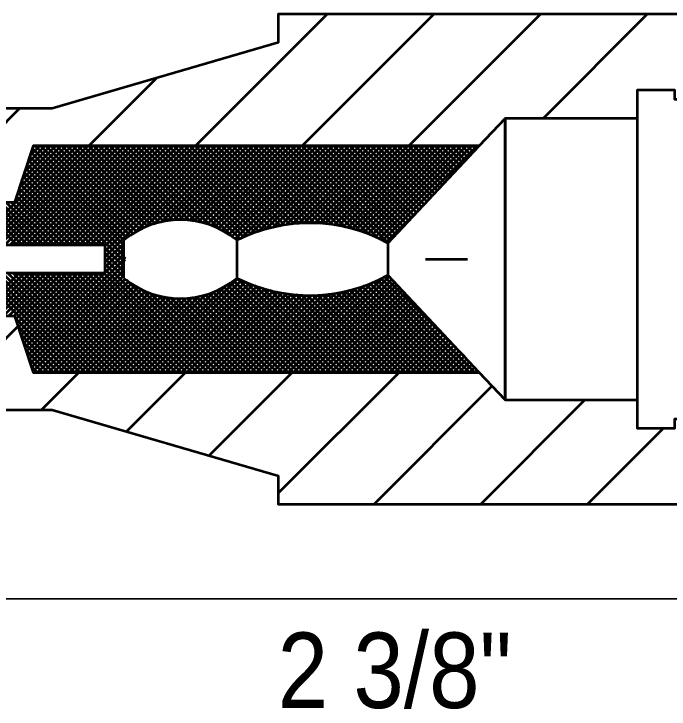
# Model space of a CAD drawing. Extents: x -1 to 679, y 0 to 440.
# Drawn here: x 477.92 to 495.29, y 208.75 to 227.17 of the extents above; entities that cross this region are included whole.
import ezdxf

# ---------------------------------------------------------------- set-up
doc = ezdxf.new("R2010")
doc.units = 0
doc.header["$LTSCALE"] = 0.8
doc.layers.add('1', color=7, linetype='Continuous', lineweight=53)

msp = doc.modelspace()

# ---------------------------------------------------------------- linework, layer by layer
at = {"layer": '1'}
for p, q in [((482.7369, 223.6716), (486.2369, 227.1716)), ((485.5653, 223.6716), (489.0653, 227.1716)), ((488.3938, 223.6716), (491.8938, 227.1716)), ((491.9503, 224.3997), (494.7222, 227.1716)), ((479.9085, 223.6716), (481.7207, 225.4837)), ((475.5801, 222.1716), (478.0801, 224.6716)), ((490.9453, 224.3997), (490.2599, 223.6716)), ((494.4453, 224.3997), (494.4453, 216.9434)), ((476.8324, 221.0466), (479.4574, 223.6716)), ((476.9738, 221.0466), (479.5988, 223.6716)), ((477.1153, 221.0466), (479.7403, 223.6716)), ((477.2567, 221.0466), (479.8817, 223.6716)), ((477.3981, 221.0466), (480.0231, 223.6716)), ((477.5396, 221.0466), (480.1646, 223.6716)), ((477.681, 221.0466), (480.306, 223.6716)), ((477.8224, 221.0466), (480.4474, 223.6716)), ((477.9638, 221.0466), (480.5888, 223.6716)), ((477.996, 222.3516), (479.316, 223.6716)), ((478.0667, 222.5637), (479.1746, 223.6716)), ((478.1053, 221.0466), (480.7303, 223.6716)), ((478.1374, 222.7758), (479.0332, 223.6716)), ((478.2081, 222.9879), (478.8918, 223.6716)), ((478.2467, 221.0466), (480.8717, 223.6716)), ((478.2788, 223.2001), (478.7503, 223.6716)), ((478.3496, 223.4123), (478.6089, 223.6716)), ((478.3881, 221.0466), (481.0131, 223.6716)), ((480.8408, 221.1752), (478.4131, 223.6029)), ((478.4203, 223.6243), (478.4675, 223.6716)), ((480.9218, 221.2357), (478.4859, 223.6716)), ((478.5295, 221.0466), (481.1545, 223.6716)), ((481.0028, 221.2961), (478.6273, 223.6716)), ((478.6709, 221.0466), (481.2959, 223.6716)), ((481.0887, 221.3517), (478.7688, 223.6716)), ((478.8123, 221.0466), (481.4373, 223.6716)), ((481.1773, 221.4044), (478.9102, 223.6716)), ((478.9537, 221.0466), (481.5787, 223.6716)), ((481.2681, 221.4551), (479.0516, 223.6716)), ((479.0952, 221.0466), (481.7202, 223.6716)), ((481.3648, 221.4997), (479.193, 223.6716)), ((479.2366, 221.0466), (481.8616, 223.6716)), ((481.4617, 221.5443), (479.3344, 223.6716)), ((479.378, 221.0466), (482.003, 223.6716)), ((481.5668, 221.5806), (479.4758, 223.6716)), ((479.5194, 221.0466), (482.1444, 223.6716)), ((481.6724, 221.6164), (479.6172, 223.6716)), ((479.6608, 221.0466), (482.2858, 223.6716)), ((481.7852, 221.645), (479.7587, 223.6716)), ((479.8022, 221.0466), (482.4272, 223.6716)), ((481.9006, 221.6711), (479.9001, 223.6716)), ((479.9437, 221.0466), (482.5687, 223.6716)), ((482.0233, 221.6898), (480.0415, 223.6716)), ((480.0852, 221.0466), (482.7102, 223.6716)), ((482.1498, 221.7047), (480.1829, 223.6716)), ((480.2266, 221.0466), (482.8516, 223.6716)), ((482.286, 221.7099), (480.3243, 223.6716)), ((480.336, 221.0146), (482.993, 223.6716)), ((480.336, 220.8732), (483.1344, 223.6716)), ((480.336, 220.7318), (483.2758, 223.6716)), ((482.4257, 221.7117), (480.4657, 223.6716)), ((482.5811, 221.6977), (480.6072, 223.6716)), ((482.7453, 221.6748), (480.7486, 223.6716)), ((482.9232, 221.6384), (480.89, 223.6716)), ((483.1284, 221.5747), (481.0315, 223.6716)), ((481.11, 221.3643), (483.4172, 223.6716)), ((483.3722, 221.4723), (481.1729, 223.6716)), ((483.7456, 221.2403), (481.3143, 223.6716)), ((481.4055, 221.5184), (483.5587, 223.6716)), ((483.9193, 221.2079), (481.4557, 223.6716)), ((484.0178, 221.2509), (481.5972, 223.6716)), ((481.6308, 221.6023), (483.7001, 223.6716)), ((484.1163, 221.2938), (481.7386, 223.6716)), ((481.8236, 221.6537), (483.8415, 223.6716)), ((484.2147, 221.3368), (481.88, 223.6716)), ((481.9981, 221.6867), (483.9829, 223.6716)), ((484.319, 221.374), (482.0214, 223.6716)), ((482.1584, 221.7057), (484.1243, 223.6716)), ((484.4264, 221.408), (482.1628, 223.6716)), ((484.5338, 221.442), (482.3042, 223.6716)), ((482.3043, 221.7102), (484.2657, 223.6716)), ((482.4457, 221.7102), (484.4072, 223.6716)), ((484.6412, 221.476), (482.4457, 223.6716)), ((482.5752, 221.6983), (484.5486, 223.6716)), ((484.7551, 221.5036), (482.5871, 223.6716)), ((482.7019, 221.6835), (484.69, 223.6716)), ((484.8725, 221.5276), (482.7285, 223.6716)), ((482.8199, 221.66), (484.8314, 223.6716)), ((484.9899, 221.5517), (482.8699, 223.6716)), ((482.9358, 221.6345), (484.9728, 223.6716)), ((485.1072, 221.5757), (483.0113, 223.6716)), ((483.0437, 221.601), (485.1143, 223.6716)), ((483.1513, 221.5673), (485.2557, 223.6716)), ((485.2347, 221.5897), (483.1527, 223.6716)), ((483.2502, 221.5247), (485.3972, 223.6716)), ((485.3636, 221.6022), (483.2942, 223.6716)), ((483.3492, 221.4822), (485.5386, 223.6716)), ((485.4924, 221.6147), (483.4356, 223.6716)), ((483.4419, 221.4335), (485.68, 223.6716)), ((483.5325, 221.3827), (485.8214, 223.6716)), ((485.6267, 221.622), (483.5771, 223.6716)), ((483.6202, 221.329), (485.9628, 223.6716)), ((483.7031, 221.2704), (486.1042, 223.6716)), ((485.7692, 221.6209), (483.7185, 223.6716)), ((483.7859, 221.2118), (486.2457, 223.6716)), ((485.9117, 221.6198), (483.8599, 223.6716)), ((483.9266, 221.2111), (486.3871, 223.6716)), ((486.0579, 221.6149), (484.0013, 223.6716)), ((486.2173, 221.597), (484.1427, 223.6716)), ((484.1774, 221.3205), (486.5285, 223.6716)), ((486.3767, 221.579), (484.2842, 223.6716)), ((484.397, 221.3987), (486.6699, 223.6716)), ((486.5452, 221.552), (484.4256, 223.6716)), ((486.7266, 221.512), (484.567, 223.6716)), ((484.6039, 221.4642), (486.8113, 223.6716)), ((486.9081, 221.4719), (484.7084, 223.6716)), ((484.7924, 221.5112), (486.9527, 223.6716)), ((487.1197, 221.4017), (484.8498, 223.6716)), ((484.9702, 221.5476), (487.0942, 223.6716)), ((487.3317, 221.3311), (484.9912, 223.6716)), ((487.5892, 221.215), (485.1327, 223.6716)), ((485.1449, 221.5809), (487.2356, 223.6716)), ((487.8426, 221.1031), (485.2741, 223.6716)), ((485.3016, 221.5962), (487.377, 223.6716)), ((487.9112, 221.1759), (485.4155, 223.6716)), ((485.4583, 221.6114), (487.5184, 223.6716)), ((487.9797, 221.2488), (485.5569, 223.6716)), ((485.6104, 221.6221), (487.6599, 223.6716)), ((488.0483, 221.3217), (485.6983, 223.6716)), ((485.7507, 221.6211), (487.8013, 223.6716)), ((488.1168, 221.3945), (485.8397, 223.6716)), ((485.8911, 221.62), (487.9427, 223.6716)), ((488.1854, 221.4673), (485.9812, 223.6716)), ((486.0306, 221.618), (488.0842, 223.6716)), ((488.254, 221.5402), (486.1227, 223.6716)), ((486.1577, 221.6037), (488.2256, 223.6716)), ((488.3226, 221.6131), (486.2641, 223.6716)), ((486.2847, 221.5893), (488.367, 223.6716)), ((488.3912, 221.6859), (486.4055, 223.6716)), ((486.4118, 221.575), (488.5084, 223.6716)), ((486.5329, 221.5547), (488.6498, 223.6716)), ((488.4597, 221.7587), (486.5469, 223.6716)), ((486.6488, 221.5291), (488.7912, 223.6716)), ((488.5282, 221.8316), (486.6883, 223.6716)), ((486.7647, 221.5036), (488.9327, 223.6716)), ((488.5968, 221.9045), (486.8297, 223.6716)), ((486.8805, 221.478), (489.0741, 223.6716)), ((488.6654, 221.9773), (486.9712, 223.6716)), ((486.9892, 221.4452), (489.2155, 223.6716)), ((487.0952, 221.4099), (489.3569, 223.6716)), ((488.734, 222.0502), (487.1126, 223.6716)), ((487.2013, 221.3746), (489.4983, 223.6716)), ((488.8026, 222.123), (487.254, 223.6716)), ((487.3074, 221.3392), (489.6397, 223.6716)), ((488.8711, 222.1959), (487.3954, 223.6716)), ((487.4072, 221.2977), (489.7812, 223.6716)), ((487.5045, 221.2535), (489.9226, 223.6716)), ((488.9397, 222.2687), (487.5368, 223.6716)), ((487.6017, 221.2093), (490.064, 223.6716)), ((489.0082, 222.3416), (487.6782, 223.6716)), ((487.699, 221.1652), (490.2055, 223.6716)), ((489.0768, 222.4144), (487.8197, 223.6716)), ((487.836, 221.0961), (490.26, 223.6716)), ((489.1454, 222.4873), (487.9611, 223.6716)), ((489.2139, 222.5602), (488.1025, 223.6716)), ((489.2825, 222.633), (488.2439, 223.6716)), ((489.3511, 222.7058), (488.3853, 223.6716)), ((489.4197, 222.7788), (488.5268, 223.6716)), ((489.4882, 222.8516), (488.6683, 223.6716)), ((489.5568, 222.9244), (488.8097, 223.6716)), ((489.6253, 222.9972), (488.9511, 223.6716)), ((489.6939, 223.0702), (489.0925, 223.6716)), ((489.7625, 223.143), (489.2339, 223.6716)), ((489.8311, 223.2158), (489.3753, 223.6716)), ((489.8997, 223.2887), (489.5168, 223.6716)), ((489.9682, 223.3616), (489.6582, 223.6716)), ((490.0367, 223.4344), (489.7996, 223.6716)), ((490.1053, 223.5072), (489.941, 223.6716)), ((490.1739, 223.5801), (490.0824, 223.6716)), ((490.2425, 223.653), (490.2238, 223.6716)), ((480.836, 220.8972), (478.3424, 223.3908)), ((480.836, 221.0386), (478.3777, 223.4968)), ((480.836, 220.6143), (478.2717, 223.1787)), ((480.836, 220.7558), (478.3071, 223.2848)), ((480.1209, 221.0466), (478.201, 222.9665)), ((480.2623, 221.0466), (478.2363, 223.0726)), ((479.9795, 221.0466), (478.1657, 222.8605)), ((479.6967, 221.0466), (478.0949, 222.6483)), ((479.8381, 221.0466), (478.1302, 222.7544)), ((479.4138, 221.0466), (478.0242, 222.4362)), ((479.5553, 221.0466), (478.0596, 222.5422)), ((479.131, 221.0466), (477.9535, 222.2241)), ((479.2724, 221.0466), (477.9888, 222.3302)), ((477.9996, 221.0466), (476.8746, 222.1716)), ((478.141, 221.0466), (477.016, 222.1716)), ((478.2824, 221.0466), (477.1574, 222.1716)), ((478.4238, 221.0466), (477.2988, 222.1716)), ((478.5653, 221.0466), (477.4403, 222.1716)), ((478.7067, 221.0466), (477.5817, 222.1716)), ((478.8482, 221.0466), (477.7232, 222.1716)), ((478.9896, 221.0466), (477.8646, 222.1716)), ((487.7938, 221.1186), (488.8698, 222.1946)), ((480.836, 220.1716), (480.836, 221.1716)), ((483.836, 221.1716), (483.836, 220.1716)), ((480.336, 220.5903), (480.836, 221.0903)), ((480.836, 220.4729), (480.336, 220.9729)), ((480.336, 220.4489), (480.836, 220.9489)), ((487.836, 221.0961), (487.836, 220.2471)), ((480.836, 220.3315), (480.336, 220.8315)), ((480.336, 220.3075), (480.836, 220.8075)), ((478.2874, 218.1174), (480.836, 220.6661)), ((480.836, 220.1901), (480.336, 220.6901)), ((488.836, 220.6716), (489.9453, 220.6716)), ((478.3227, 218.0114), (480.836, 220.5247)), ((478.3581, 217.9053), (480.836, 220.3833)), ((483.2131, 217.6716), (480.336, 220.5487)), ((483.0717, 217.6716), (480.336, 220.4073)), ((479.5362, 217.6716), (476.9112, 220.2966)), ((476.9373, 219.1716), (478.0623, 220.2966)), ((479.6776, 217.6716), (477.0526, 220.2966)), ((477.0787, 219.1716), (478.2037, 220.2966)), ((479.819, 217.6716), (477.194, 220.2966)), ((477.2202, 219.1716), (478.3452, 220.2966)), ((479.9604, 217.6716), (477.3354, 220.2966)), ((477.3616, 219.1716), (478.4866, 220.2966)), ((480.1018, 217.6716), (477.4768, 220.2966)), ((477.503, 219.1716), (478.628, 220.2966)), ((480.2432, 217.6716), (477.6182, 220.2966)), ((477.6444, 219.1716), (478.7694, 220.2966)), ((480.3847, 217.6716), (477.7597, 220.2966)), ((477.7858, 219.1716), (478.9108, 220.2966)), ((480.5261, 217.6716), (477.9011, 220.2966)), ((477.9272, 219.1716), (479.0522, 220.2966)), ((477.9692, 219.0721), (479.1937, 220.2966)), ((478.0045, 218.966), (479.3352, 220.2966)), ((478.0399, 218.8599), (479.4766, 220.2966)), ((480.6675, 217.6716), (478.0425, 220.2966)), ((478.0752, 218.7538), (479.618, 220.2966)), ((478.1106, 218.6478), (479.7594, 220.2966)), ((478.1459, 218.5417), (479.9008, 220.2966)), ((478.1813, 218.4357), (480.0422, 220.2966)), ((480.8089, 217.6716), (478.1839, 220.2966)), ((478.2167, 218.3296), (480.1837, 220.2966)), ((478.252, 218.2235), (480.3251, 220.2966)), ((480.9503, 217.6716), (478.3253, 220.2966)), ((478.3934, 217.7993), (480.836, 220.2418)), ((481.0917, 217.6716), (478.4667, 220.2966)), ((481.2332, 217.6716), (478.6082, 220.2966)), ((481.3746, 217.6716), (478.7496, 220.2966)), ((481.516, 217.6716), (478.891, 220.2966)), ((481.6574, 217.6716), (479.0324, 220.2966)), ((481.7988, 217.6716), (479.1738, 220.2966)), ((481.9403, 217.6716), (479.3153, 220.2966)), ((482.0817, 217.6716), (479.4567, 220.2966)), ((482.2232, 217.6716), (479.5982, 220.2966)), ((482.3646, 217.6716), (479.7396, 220.2966)), ((482.506, 217.6716), (479.881, 220.2966)), ((482.6474, 217.6716), (480.0224, 220.2966)), ((482.7888, 217.6716), (480.1638, 220.2966)), ((482.9303, 217.6716), (480.3053, 220.2966)), ((485.3368, 217.6716), (487.873, 220.2078)), ((489.8736, 218.0822), (487.7505, 220.2053)), ((478.4288, 217.6932), (480.8753, 220.1397)), ((478.5486, 217.6716), (480.9577, 220.0807)), ((478.69, 217.6716), (481.0406, 220.0222)), ((483.3545, 217.6716), (480.9155, 220.1106)), ((481.377, 217.6716), (483.8636, 220.1582)), ((481.5184, 217.6716), (483.9588, 220.1119)), ((481.6599, 217.6716), (484.0591, 220.0708)), ((481.8013, 217.6716), (484.1599, 220.0302)), ((486.0415, 217.6716), (483.6673, 220.0457)), ((486.1829, 217.6716), (483.7483, 220.1062)), ((486.3243, 217.6716), (483.8293, 220.1666)), ((486.4657, 217.6716), (484.0716, 220.0658)), ((485.054, 217.6716), (487.4325, 220.0501)), ((485.1954, 217.6716), (487.7086, 220.1847)), ((485.4783, 217.6716), (487.9416, 220.1349)), ((485.6197, 217.6716), (488.0102, 220.0621)), ((489.7185, 217.6716), (487.3647, 220.0253)), ((489.8599, 217.6716), (487.4656, 220.0659)), ((490.0013, 217.6716), (487.5605, 220.1123)), ((490.1427, 217.6716), (487.6555, 220.1588)), ((478.8314, 217.6716), (481.1272, 219.9673)), ((478.9728, 217.6716), (481.2178, 219.9165)), ((479.1143, 217.6716), (481.3095, 219.8667)), ((479.2557, 217.6716), (481.4083, 219.8243)), ((481.2356, 217.6716), (483.5147, 219.9507)), ((483.4959, 217.6716), (481.2933, 219.8742)), ((481.9427, 217.6716), (484.2607, 219.9896)), ((482.0842, 217.6716), (484.3616, 219.949)), ((482.2256, 217.6716), (484.4697, 219.9158)), ((482.367, 217.6716), (484.5797, 219.8844)), ((482.5084, 217.6716), (484.6898, 219.853)), ((482.6498, 217.6716), (484.7997, 219.8216)), ((485.4758, 217.6716), (483.3049, 219.8425)), ((485.6172, 217.6716), (483.4017, 219.8871)), ((485.7587, 217.6716), (483.4927, 219.9376)), ((485.9001, 217.6716), (483.5813, 219.9903)), ((486.6072, 217.6716), (484.3083, 219.9704)), ((486.7486, 217.6716), (484.5182, 219.9019)), ((484.6298, 217.6716), (486.8027, 219.8446)), ((486.89, 217.6716), (484.7162, 219.8454)), ((484.7712, 217.6716), (486.9913, 219.8918)), ((484.9126, 217.6716), (487.2097, 219.9688)), ((485.7611, 217.6716), (488.0787, 219.9892)), ((485.9025, 217.6716), (488.1472, 219.9163)), ((486.0439, 217.6716), (488.2158, 219.8435)), ((488.8699, 217.6716), (486.7182, 219.8233)), ((489.0113, 217.6716), (486.8313, 219.8517)), ((489.1527, 217.6716), (486.9443, 219.88)), ((489.2942, 217.6716), (487.0539, 219.9118)), ((489.4356, 217.6716), (487.1575, 219.9497)), ((489.5771, 217.6716), (487.2612, 219.9875)), ((479.3972, 217.6716), (481.5072, 219.7817)), ((479.5386, 217.6716), (481.6137, 219.7467)), ((479.68, 217.6716), (481.7216, 219.7132)), ((479.8214, 217.6716), (481.8362, 219.6863)), ((479.9628, 217.6716), (481.9541, 219.6628)), ((480.1042, 217.6716), (482.0792, 219.6466)), ((480.2457, 217.6716), (482.2087, 219.6346)), ((480.5285, 217.6716), (482.4918, 219.6349)), ((480.6699, 217.6716), (482.6522, 219.6538)), ((480.8113, 217.6716), (482.8237, 219.6839)), ((480.9527, 217.6716), (483.0122, 219.7311)), ((481.0942, 217.6716), (483.231, 219.8084)), ((483.6373, 217.6716), (481.539, 219.7699)), ((483.7788, 217.6716), (481.7442, 219.7062)), ((483.9202, 217.6716), (481.9227, 219.6691)), ((484.0616, 217.6716), (482.0874, 219.6457)), ((484.4859, 217.6716), (482.5192, 219.6382)), ((484.6273, 217.6716), (482.6457, 219.6531)), ((484.7688, 217.6716), (482.7688, 219.6715)), ((482.7912, 217.6716), (484.9192, 219.7995)), ((484.9102, 217.6716), (482.8842, 219.6976)), ((482.9327, 217.6716), (485.0395, 219.7784)), ((485.0516, 217.6716), (482.9972, 219.7259)), ((483.0741, 217.6716), (485.1598, 219.7573)), ((485.193, 217.6716), (483.1028, 219.7618)), ((485.3344, 217.6716), (483.2081, 219.7978)), ((483.2155, 217.6716), (485.2832, 219.7392)), ((483.3569, 217.6716), (485.4155, 219.7302)), ((483.4983, 217.6716), (485.5478, 219.721)), ((483.6397, 217.6716), (485.6801, 219.7119)), ((483.7812, 217.6716), (485.8252, 219.7156)), ((483.9226, 217.6716), (485.9719, 219.7208)), ((484.064, 217.6716), (486.1186, 219.7261)), ((484.2055, 217.6716), (486.2806, 219.7467)), ((484.3469, 217.6716), (486.4453, 219.77)), ((484.4883, 217.6716), (486.614, 219.7973)), ((487.0315, 217.6716), (484.9002, 219.8028)), ((487.1729, 217.6716), (485.0718, 219.7728)), ((487.3143, 217.6716), (485.2432, 219.7427)), ((487.4557, 217.6716), (485.3958, 219.7315)), ((487.5972, 217.6716), (485.5477, 219.721)), ((487.7386, 217.6716), (485.6991, 219.711)), ((487.88, 217.6716), (485.8357, 219.7159)), ((488.0214, 217.6716), (485.9722, 219.7208)), ((488.1628, 217.6716), (486.1087, 219.7258)), ((486.1853, 217.6716), (488.2844, 219.7707)), ((488.3042, 217.6716), (486.2355, 219.7403)), ((486.3268, 217.6716), (488.353, 219.6977)), ((488.4457, 217.6716), (486.3594, 219.7578)), ((488.5871, 217.6716), (486.4832, 219.7754)), ((488.7285, 217.6716), (486.6051, 219.7951)), ((480.3871, 217.6716), (482.3483, 219.6327)), ((484.203, 217.6716), (482.2432, 219.6314)), ((484.3444, 217.6716), (482.3828, 219.6333)), ((486.4682, 217.6716), (488.4216, 219.6249)), ((486.6096, 217.6716), (488.4901, 219.5521)), ((486.7511, 217.6716), (488.5587, 219.4792)), ((486.8925, 217.6716), (488.6273, 219.4063)), ((487.0339, 217.6716), (488.6958, 219.3335)), ((479.3947, 217.6716), (477.9567, 219.1097)), ((487.1753, 217.6716), (488.7644, 219.2607)), ((487.3167, 217.6716), (488.833, 219.1878)), ((487.4582, 217.6716), (488.9015, 219.115)), ((479.2532, 217.6716), (478.0273, 218.8975)), ((487.5996, 217.6716), (488.9701, 219.0421)), ((487.741, 217.6716), (489.0387, 218.9692)), ((475.819, 216.6716), (478.0317, 218.8843)), ((487.8824, 217.6716), (489.1072, 218.8964)), ((488.0238, 217.6716), (489.1758, 218.8236)), ((488.1652, 217.6716), (489.2443, 218.7507)), ((479.1118, 217.6716), (478.0981, 218.6854)), ((488.3067, 217.6716), (489.3129, 218.6778)), ((488.4481, 217.6716), (489.3815, 218.605)), ((488.5895, 217.6716), (489.4501, 218.5322)), ((478.9704, 217.6716), (478.1687, 218.4732)), ((488.7309, 217.6716), (489.5187, 218.4592)), ((488.8723, 217.6716), (489.5872, 218.3864)), ((478.829, 217.6716), (478.2395, 218.2611)), ((489.0137, 217.6716), (489.6558, 218.3136)), ((489.1552, 217.6716), (489.7243, 218.2407)), ((489.2967, 217.6716), (489.7929, 218.1678)), ((478.6876, 217.6716), (478.3102, 218.049)), ((489.4381, 217.6716), (489.8615, 218.095)), ((489.5795, 217.6716), (489.9301, 218.0222)), ((478.5462, 217.6716), (478.3809, 217.8368)), ((489.7209, 217.6716), (489.9986, 217.9493)), ((489.8623, 217.6716), (490.0672, 217.8764)), ((490.0037, 217.6716), (490.1357, 217.8036)), ((478.6474, 216.6716), (479.6474, 217.6716)), ((480.9023, 216.0981), (482.4758, 217.6716)), ((483.0921, 215.4594), (485.3043, 217.6716)), ((484.936, 214.4748), (488.1327, 217.6716)), ((490.1452, 217.6716), (490.2043, 217.7308)), ((487.4612, 214.1716), (490.5999, 217.3104)), ((490.2896, 214.1716), (493.0614, 216.9434)), ((493.118, 214.1716), (495.1398, 216.1934))]:
    msp.add_line(p, q, dxfattribs=at)
at = {"layer": '1', "lineweight": 35}
msp.add_line((470.936, 211.6716), (504.936, 211.6716), dxfattribs=at)
at = {"layer": '1'}
for points in [[(470.936, 222.1716), (470.936, 224.6716), (478.936, 224.6716), (484.936, 226.4216), (484.936, 227.1716), (504.936, 227.1716), (504.936, 225.5357)], [(496.4453, 223.8997), (496.4453, 224.8997), (495.4453, 224.8997), (495.4453, 225.1497), (494.4453, 225.1497), (494.4453, 224.3997), (490.9453, 224.3997)], [(490.26, 223.6716), (478.436, 223.6716), (477.936, 222.1716), (470.936, 222.1716), (460.936, 222.1716), (460.936, 221.4216), (452.936, 221.4216), (452.936, 219.9216), (460.936, 219.9216), (460.936, 219.1716), (470.936, 219.1716), (477.936, 219.1716), (478.436, 217.6716), (490.26, 217.6716), (490.9453, 216.9434), (490.9453, 224.3997)], [(490.2599, 223.6716), (490.9453, 224.3997), (490.9453, 216.9434), (490.26, 217.6716), (487.836, 220.2471)], [(490.9453, 216.9434), (494.4453, 216.9434), (494.4453, 216.1934), (495.4453, 216.1934), (495.4453, 216.4434), (496.4453, 216.4434), (496.4453, 217.4434)], [(504.936, 215.8075), (504.936, 214.1716), (484.936, 214.1716), (484.936, 214.9216), (478.936, 216.6716), (470.936, 216.6716)]]:
    msp.add_lwpolyline(points, dxfattribs=at)
msp.add_lwpolyline([(461.436, 220.2966), (461.436, 221.0466), (480.336, 221.0466), (480.336, 220.2966)], close=True, dxfattribs=at)
for centre, radius, start, end in [((482.336, 219.3669), 2.3467, 50.26743, 129.73258), ((485.7639, 217.3159), 4.3108, 61.27121, 116.56614), ((480.8918, 220.6699), 0.0559, 113.08005, 246.91995), ((485.7649, 223.9741), 4.2638, 243.10234, 299.06032), ((482.336, 221.9763), 2.3467, 230.26742, 309.73257)]:
    msp.add_arc(centre, radius, start, end, dxfattribs=at)

# ---------------------------------------------------------------- texts
at = {"layer": '1', "width": 0.9}
msp.add_text('2 3/8"', height=2, dxfattribs=at).set_placement((484.9151, 208.7743))

doc.saveas('drawing.dxf')
